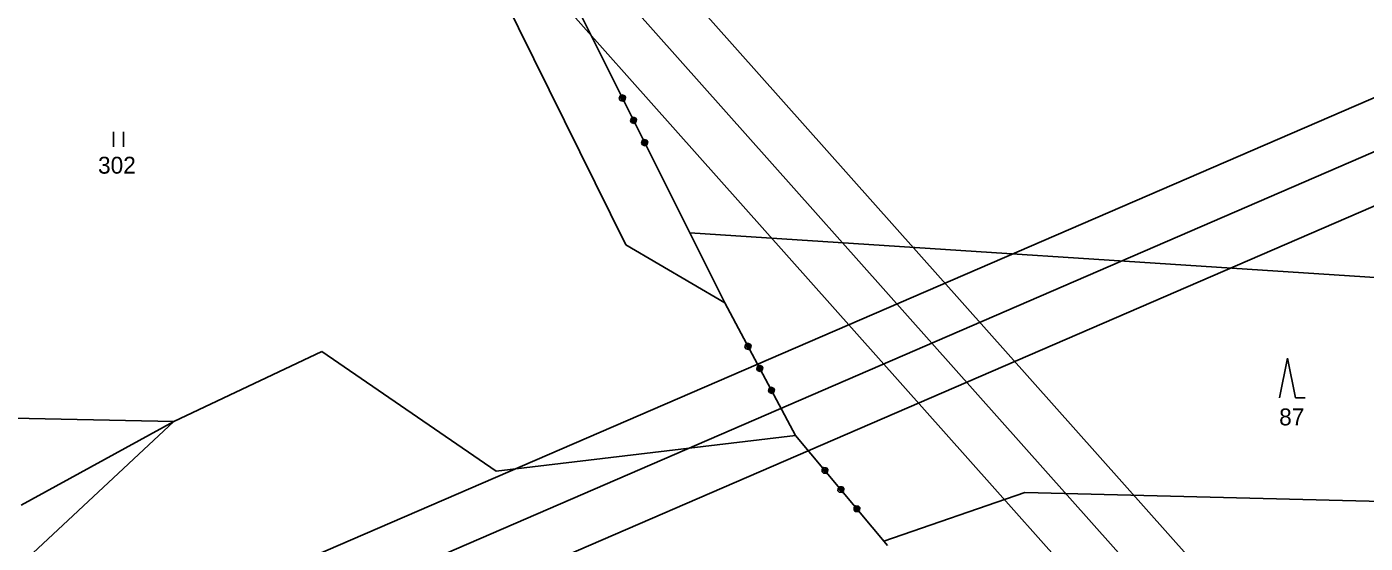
# Model space of a CAD drawing. Extents: x -866656 to -858817, y -1041816 to -1038653.
# Drawn here: x -865224.7 to -865090.2, y -1040508.5 to -1040456.6 of the extents above; entities that cross this region are included whole.
import ezdxf

# ---------------------------------------------------------------- set-up
doc = ezdxf.new("R2010")
doc.units = 0
for name, color, linetype in [('tisk ramy', 7, 'Continuous'), ('Vrstva 1', 7, 'Continuous'), ('Vrstva 3', 7, 'Continuous')]:
    doc.layers.add(name, color=color, linetype=linetype)

msp = doc.modelspace()

# ---------------------------------------------------------------- linework, layer by layer
at = {"layer": 'tisk ramy'}
for points in [[(-865732.63, -1039823.16), (-864894.8, -1040764.23), (-864672.98, -1040566.75), (-865510.81, -1039625.68)], [(-865511.22, -1039632.74), (-864680.04, -1040566.34), (-864894.39, -1040757.18), (-865725.57, -1039823.57)], [(-865718.52, -1039823.98), (-865030.3, -1040597.01), (-864823.41, -1040412.82), (-865511.63, -1039639.79)], [(-865511.63, -1039639.79), (-864823.41, -1040412.82), (-865030.3, -1040597.01), (-865718.52, -1039823.98)], [(-865224.28, -1040522.07), (-864724.07, -1041678.52), (-864451.49, -1041560.62), (-864951.69, -1040404.17)], [(-864954.3, -1040410.74), (-864458.06, -1041558.01), (-864721.47, -1041671.94), (-865217.7, -1040524.67)], [(-865211.14, -1040527.28), (-864800.25, -1041477.22), (-864546.01, -1041367.26), (-864956.9, -1040417.31)], [(-864956.9, -1040417.31), (-864546.01, -1041367.26), (-864800.25, -1041477.22), (-865211.14, -1040527.28)]]:
    msp.add_lwpolyline(points, close=True, dxfattribs=at)
at = {"layer": 'Vrstva 1'}
for p, q in [((-865164.46, -1040478.49), (-865186.01, -1040434.88)), ((-865215.96, -1040468.62), (-865215.96, -1040467.12)), ((-865214.96, -1040467.12), (-865214.96, -1040468.62)), ((-865058.05, -1040483.78), (-865158.05, -1040477.27)), ((-865154.52, -1040484.32), (-865164.46, -1040478.49)), ((-865209.89, -1040496.23), (-865195.03, -1040489.18)), ((-865195.03, -1040489.18), (-865177.49, -1040501.21)), ((-865098.78, -1040493.85), (-865097.98, -1040489.85)), ((-865097.98, -1040489.85), (-865097.18, -1040493.85)), ((-865097.18, -1040493.85), (-865096.18, -1040493.85)), ((-865234.53, -1040495.7), (-865209.89, -1040496.23)), ((-865225.24, -1040504.64), (-865209.89, -1040496.23)), ((-865209.89, -1040496.23), (-865224.07, -1040509.48)), ((-865177.49, -1040501.21), (-865147.41, -1040497.64)), ((-865124.38, -1040503.38), (-865138.53, -1040508.25)), ((-865078.37, -1040504.54), (-865124.38, -1040503.38))]:
    msp.add_line(p, q, dxfattribs=at)
at = {"layer": 'Vrstva 3'}
for p, q in [((-865172.79, -1040447.78), (-865154.52, -1040484.32)), ((-865172.79, -1040447.78), (-865154.52, -1040484.32)), ((-865165.13, -1040463.77), (-865165.04, -1040463.5)), ((-865165.13, -1040463.77), (-865165.04, -1040463.5)), ((-865165.04, -1040463.95), (-865165.13, -1040463.77)), ((-865165.04, -1040463.95), (-865165.13, -1040463.77)), ((-865165.04, -1040463.5), (-865164.86, -1040463.41)), ((-865165.04, -1040463.5), (-865164.86, -1040463.41)), ((-865165.04, -1040463.72), (-865164.68, -1040463.55)), ((-865165.04, -1040463.72), (-865164.68, -1040463.55)), ((-865165, -1040463.59), (-865165.04, -1040463.72)), ((-865165, -1040463.59), (-865165.04, -1040463.72)), ((-865164.77, -1040464.04), (-865165.04, -1040463.95)), ((-865164.77, -1040464.04), (-865165.04, -1040463.95)), ((-865164.82, -1040463.5), (-865165, -1040463.59)), ((-865164.82, -1040463.5), (-865165, -1040463.59)), ((-865164.64, -1040463.64), (-865165, -1040463.81)), ((-865164.64, -1040463.64), (-865165, -1040463.81)), ((-865164.59, -1040463.72), (-865164.95, -1040463.9)), ((-865164.59, -1040463.72), (-865164.95, -1040463.9)), ((-865164.95, -1040463.9), (-865164.82, -1040463.95)), ((-865164.95, -1040463.9), (-865164.82, -1040463.95)), ((-865164.86, -1040463.41), (-865164.59, -1040463.5)), ((-865164.86, -1040463.41), (-865164.59, -1040463.5)), ((-865164.82, -1040463.95), (-865164.64, -1040463.86)), ((-865164.82, -1040463.95), (-865164.64, -1040463.86)), ((-865164.59, -1040463.95), (-865164.77, -1040464.04)), ((-865164.59, -1040463.95), (-865164.77, -1040464.04)), ((-865164.68, -1040463.55), (-865164.59, -1040463.72)), ((-865164.68, -1040463.55), (-865164.59, -1040463.72)), ((-865164.59, -1040463.5), (-865164.5, -1040463.68)), ((-865164.59, -1040463.5), (-865164.5, -1040463.68)), ((-865164.5, -1040463.68), (-865164.59, -1040463.95)), ((-865164.5, -1040463.68), (-865164.59, -1040463.95)), ((-865164.01, -1040466.01), (-865163.92, -1040465.74)), ((-865164.01, -1040466.01), (-865163.92, -1040465.74)), ((-865163.92, -1040466.18), (-865164.01, -1040466.01)), ((-865163.92, -1040466.18), (-865164.01, -1040466.01)), ((-865163.92, -1040465.74), (-865163.74, -1040465.65)), ((-865163.92, -1040465.74), (-865163.74, -1040465.65)), ((-865163.92, -1040465.96), (-865163.57, -1040465.78)), ((-865163.92, -1040465.96), (-865163.57, -1040465.78)), ((-865163.88, -1040465.83), (-865163.92, -1040465.96)), ((-865163.88, -1040465.83), (-865163.92, -1040465.96)), ((-865163.66, -1040466.27), (-865163.92, -1040466.18)), ((-865163.66, -1040466.27), (-865163.92, -1040466.18)), ((-865163.7, -1040465.74), (-865163.88, -1040465.83)), ((-865163.7, -1040465.74), (-865163.88, -1040465.83)), ((-865163.52, -1040465.87), (-865163.88, -1040466.05)), ((-865163.52, -1040465.87), (-865163.88, -1040466.05)), ((-865163.48, -1040465.96), (-865163.83, -1040466.14)), ((-865163.48, -1040465.96), (-865163.83, -1040466.14)), ((-865163.83, -1040466.14), (-865163.7, -1040466.18)), ((-865163.83, -1040466.14), (-865163.7, -1040466.18)), ((-865163.74, -1040465.65), (-865163.48, -1040465.74)), ((-865163.74, -1040465.65), (-865163.48, -1040465.74)), ((-865163.7, -1040466.18), (-865163.52, -1040466.09)), ((-865163.7, -1040466.18), (-865163.52, -1040466.09)), ((-865163.48, -1040466.18), (-865163.66, -1040466.27)), ((-865163.48, -1040466.18), (-865163.66, -1040466.27)), ((-865163.57, -1040465.78), (-865163.48, -1040465.96)), ((-865163.57, -1040465.78), (-865163.48, -1040465.96)), ((-865163.48, -1040465.74), (-865163.39, -1040465.92)), ((-865163.48, -1040465.74), (-865163.39, -1040465.92)), ((-865163.39, -1040465.92), (-865163.48, -1040466.18)), ((-865163.39, -1040465.92), (-865163.48, -1040466.18)), ((-865162.89, -1040468.24), (-865162.81, -1040467.97)), ((-865162.89, -1040468.24), (-865162.81, -1040467.97)), ((-865162.81, -1040467.97), (-865162.63, -1040467.88)), ((-865162.81, -1040467.97), (-865162.63, -1040467.88)), ((-865162.81, -1040468.2), (-865162.45, -1040468.02)), ((-865162.81, -1040468.2), (-865162.45, -1040468.02)), ((-865162.58, -1040467.97), (-865162.76, -1040468.06)), ((-865162.58, -1040467.97), (-865162.76, -1040468.06)), ((-865162.63, -1040467.88), (-865162.36, -1040467.97)), ((-865162.63, -1040467.88), (-865162.36, -1040467.97)), ((-865162.45, -1040468.02), (-865162.36, -1040468.2)), ((-865162.45, -1040468.02), (-865162.36, -1040468.2)), ((-865162.36, -1040467.97), (-865162.27, -1040468.15)), ((-865162.36, -1040467.97), (-865162.27, -1040468.15)), ((-865162.81, -1040468.42), (-865162.89, -1040468.24)), ((-865162.81, -1040468.42), (-865162.89, -1040468.24)), ((-865162.76, -1040468.06), (-865162.81, -1040468.2)), ((-865162.76, -1040468.06), (-865162.81, -1040468.2)), ((-865162.54, -1040468.51), (-865162.81, -1040468.42)), ((-865162.54, -1040468.51), (-865162.81, -1040468.42)), ((-865162.4, -1040468.11), (-865162.76, -1040468.29)), ((-865162.4, -1040468.11), (-865162.76, -1040468.29)), ((-865162.36, -1040468.2), (-865162.71, -1040468.38)), ((-865162.36, -1040468.2), (-865162.71, -1040468.38)), ((-865162.71, -1040468.38), (-865162.58, -1040468.42)), ((-865162.71, -1040468.38), (-865162.58, -1040468.42)), ((-865162.58, -1040468.42), (-865162.4, -1040468.33)), ((-865162.58, -1040468.42), (-865162.4, -1040468.33)), ((-865162.36, -1040468.42), (-865162.54, -1040468.51)), ((-865162.36, -1040468.42), (-865162.54, -1040468.51)), ((-865162.27, -1040468.15), (-865162.36, -1040468.42)), ((-865162.27, -1040468.15), (-865162.36, -1040468.42)), ((-865154.52, -1040484.32), (-865147.41, -1040497.64)), ((-865154.52, -1040484.32), (-865147.41, -1040497.64)), ((-865152.5, -1040488.74), (-865152.42, -1040488.47)), ((-865152.5, -1040488.74), (-865152.42, -1040488.47)), ((-865152.41, -1040488.92), (-865152.5, -1040488.74)), ((-865152.41, -1040488.92), (-865152.5, -1040488.74)), ((-865152.42, -1040488.47), (-865152.24, -1040488.37)), ((-865152.42, -1040488.47), (-865152.24, -1040488.37)), ((-865152.41, -1040488.69), (-865152.06, -1040488.5)), ((-865152.41, -1040488.69), (-865152.06, -1040488.5)), ((-865152.37, -1040488.56), (-865152.41, -1040488.69)), ((-865152.37, -1040488.56), (-865152.41, -1040488.69)), ((-865152.14, -1040489), (-865152.41, -1040488.92)), ((-865152.14, -1040489), (-865152.41, -1040488.92)), ((-865152.2, -1040488.46), (-865152.37, -1040488.56)), ((-865152.2, -1040488.46), (-865152.37, -1040488.56)), ((-865152.01, -1040488.59), (-865152.36, -1040488.78)), ((-865152.01, -1040488.59), (-865152.36, -1040488.78)), ((-865151.96, -1040488.68), (-865152.32, -1040488.87)), ((-865151.96, -1040488.68), (-865152.32, -1040488.87)), ((-865152.32, -1040488.87), (-865152.18, -1040488.91)), ((-865152.32, -1040488.87), (-865152.18, -1040488.91)), ((-865152.24, -1040488.37), (-865151.97, -1040488.46)), ((-865152.24, -1040488.37), (-865151.97, -1040488.46)), ((-865152.18, -1040488.91), (-865152.01, -1040488.82)), ((-865152.18, -1040488.91), (-865152.01, -1040488.82)), ((-865151.96, -1040488.9), (-865152.14, -1040489)), ((-865151.96, -1040488.9), (-865152.14, -1040489)), ((-865152.06, -1040488.5), (-865151.96, -1040488.68)), ((-865152.06, -1040488.5), (-865151.96, -1040488.68)), ((-865151.97, -1040488.46), (-865151.88, -1040488.63)), ((-865151.97, -1040488.46), (-865151.88, -1040488.63)), ((-865151.88, -1040488.63), (-865151.96, -1040488.9)), ((-865151.88, -1040488.63), (-865151.96, -1040488.9)), ((-865151.32, -1040490.94), (-865151.24, -1040490.67)), ((-865151.32, -1040490.94), (-865151.24, -1040490.67)), ((-865151.24, -1040490.67), (-865151.07, -1040490.58)), ((-865151.24, -1040490.67), (-865151.07, -1040490.58)), ((-865151.23, -1040490.9), (-865150.88, -1040490.71)), ((-865151.23, -1040490.9), (-865150.88, -1040490.71)), ((-865151.19, -1040490.76), (-865151.23, -1040490.9)), ((-865151.19, -1040490.76), (-865151.23, -1040490.9)), ((-865151.02, -1040490.67), (-865151.19, -1040490.76)), ((-865151.02, -1040490.67), (-865151.19, -1040490.76)), ((-865150.83, -1040490.8), (-865151.19, -1040490.98)), ((-865150.83, -1040490.8), (-865151.19, -1040490.98)), ((-865150.79, -1040490.89), (-865151.14, -1040491.07)), ((-865150.79, -1040490.89), (-865151.14, -1040491.07)), ((-865151.07, -1040490.58), (-865150.79, -1040490.66)), ((-865151.07, -1040490.58), (-865150.79, -1040490.66)), ((-865150.88, -1040490.71), (-865150.79, -1040490.89)), ((-865150.88, -1040490.71), (-865150.79, -1040490.89)), ((-865150.79, -1040490.66), (-865150.7, -1040490.84)), ((-865150.79, -1040490.66), (-865150.7, -1040490.84)), ((-865150.7, -1040490.84), (-865150.78, -1040491.11)), ((-865150.7, -1040490.84), (-865150.78, -1040491.11)), ((-865151.23, -1040491.12), (-865151.32, -1040490.94)), ((-865151.23, -1040491.12), (-865151.32, -1040490.94)), ((-865150.96, -1040491.2), (-865151.23, -1040491.12)), ((-865150.96, -1040491.2), (-865151.23, -1040491.12)), ((-865151.14, -1040491.07), (-865151.01, -1040491.11)), ((-865151.14, -1040491.07), (-865151.01, -1040491.11)), ((-865151.01, -1040491.11), (-865150.83, -1040491.02)), ((-865151.01, -1040491.11), (-865150.83, -1040491.02)), ((-865150.78, -1040491.11), (-865150.96, -1040491.2)), ((-865150.78, -1040491.11), (-865150.96, -1040491.2)), ((-865150.15, -1040493.15), (-865150.06, -1040492.88)), ((-865150.15, -1040493.15), (-865150.06, -1040492.88)), ((-865150.05, -1040493.33), (-865150.15, -1040493.15)), ((-865150.05, -1040493.33), (-865150.15, -1040493.15)), ((-865150.06, -1040492.88), (-865149.89, -1040492.79)), ((-865150.06, -1040492.88), (-865149.89, -1040492.79)), ((-865150.06, -1040493.1), (-865149.71, -1040492.91)), ((-865150.06, -1040493.1), (-865149.71, -1040492.91)), ((-865150.02, -1040492.97), (-865150.06, -1040493.1)), ((-865150.02, -1040492.97), (-865150.06, -1040493.1)), ((-865149.78, -1040493.41), (-865150.05, -1040493.33)), ((-865149.78, -1040493.41), (-865150.05, -1040493.33)), ((-865149.84, -1040492.87), (-865150.02, -1040492.97)), ((-865149.84, -1040492.87), (-865150.02, -1040492.97)), ((-865149.66, -1040493), (-865150.01, -1040493.19)), ((-865149.66, -1040493), (-865150.01, -1040493.19)), ((-865149.61, -1040493.09), (-865149.96, -1040493.28)), ((-865149.61, -1040493.09), (-865149.96, -1040493.28)), ((-865149.96, -1040493.28), (-865149.83, -1040493.32)), ((-865149.96, -1040493.28), (-865149.83, -1040493.32)), ((-865149.89, -1040492.79), (-865149.62, -1040492.87)), ((-865149.89, -1040492.79), (-865149.62, -1040492.87)), ((-865149.83, -1040493.32), (-865149.65, -1040493.23)), ((-865149.83, -1040493.32), (-865149.65, -1040493.23)), ((-865149.6, -1040493.31), (-865149.78, -1040493.41)), ((-865149.6, -1040493.31), (-865149.78, -1040493.41)), ((-865149.71, -1040492.91), (-865149.61, -1040493.09)), ((-865149.71, -1040492.91), (-865149.61, -1040493.09)), ((-865149.62, -1040492.87), (-865149.52, -1040493.04)), ((-865149.62, -1040492.87), (-865149.52, -1040493.04)), ((-865149.52, -1040493.04), (-865149.6, -1040493.31)), ((-865149.52, -1040493.04), (-865149.6, -1040493.31)), ((-865147.41, -1040497.64), (-865138.17, -1040508.68)), ((-865147.41, -1040497.64), (-865138.17, -1040508.68)), ((-865144.75, -1040501.28), (-865144.73, -1040501)), ((-865144.75, -1040501.28), (-865144.73, -1040501)), ((-865144.62, -1040501.44), (-865144.75, -1040501.28)), ((-865144.62, -1040501.44), (-865144.75, -1040501.28)), ((-865144.73, -1040501), (-865144.57, -1040500.87)), ((-865144.73, -1040501), (-865144.57, -1040500.87)), ((-865144.68, -1040501.22), (-865144.37, -1040500.96)), ((-865144.68, -1040501.22), (-865144.37, -1040500.96)), ((-865144.66, -1040501.08), (-865144.68, -1040501.22)), ((-865144.66, -1040501.08), (-865144.68, -1040501.22)), ((-865144.51, -1040500.95), (-865144.66, -1040501.08)), ((-865144.51, -1040500.95), (-865144.66, -1040501.08)), ((-865144.34, -1040501.46), (-865144.62, -1040501.44)), ((-865144.34, -1040501.46), (-865144.62, -1040501.44)), ((-865144.31, -1040501.04), (-865144.61, -1040501.29)), ((-865144.31, -1040501.04), (-865144.61, -1040501.29)), ((-865144.57, -1040500.87), (-865144.29, -1040500.9)), ((-865144.57, -1040500.87), (-865144.29, -1040500.9)), ((-865144.24, -1040501.11), (-865144.55, -1040501.37)), ((-865144.24, -1040501.11), (-865144.55, -1040501.37)), ((-865144.55, -1040501.37), (-865144.41, -1040501.38)), ((-865144.55, -1040501.37), (-865144.41, -1040501.38)), ((-865144.41, -1040501.38), (-865144.25, -1040501.26)), ((-865144.41, -1040501.38), (-865144.25, -1040501.26)), ((-865144.37, -1040500.96), (-865144.24, -1040501.11)), ((-865144.37, -1040500.96), (-865144.24, -1040501.11)), ((-865144.19, -1040501.33), (-865144.34, -1040501.46)), ((-865144.19, -1040501.33), (-865144.34, -1040501.46)), ((-865144.29, -1040500.9), (-865144.16, -1040501.05)), ((-865144.29, -1040500.9), (-865144.16, -1040501.05)), ((-865144.16, -1040501.05), (-865144.19, -1040501.33)), ((-865144.16, -1040501.05), (-865144.19, -1040501.33)), ((-865143.15, -1040503.2), (-865143.12, -1040502.92)), ((-865143.15, -1040503.2), (-865143.12, -1040502.92)), ((-865143.12, -1040502.92), (-865142.97, -1040502.79)), ((-865143.12, -1040502.92), (-865142.97, -1040502.79)), ((-865143.07, -1040503.14), (-865142.77, -1040502.88)), ((-865143.07, -1040503.14), (-865142.77, -1040502.88)), ((-865143.06, -1040502.99), (-865143.07, -1040503.14)), ((-865143.06, -1040502.99), (-865143.07, -1040503.14)), ((-865142.91, -1040502.86), (-865143.06, -1040502.99)), ((-865142.91, -1040502.86), (-865143.06, -1040502.99)), ((-865142.7, -1040502.95), (-865143.01, -1040503.21)), ((-865142.7, -1040502.95), (-865143.01, -1040503.21)), ((-865142.97, -1040502.79), (-865142.69, -1040502.81)), ((-865142.97, -1040502.79), (-865142.69, -1040502.81)), ((-865142.77, -1040502.88), (-865142.64, -1040503.03)), ((-865142.77, -1040502.88), (-865142.64, -1040503.03)), ((-865142.69, -1040502.81), (-865142.56, -1040502.97)), ((-865142.69, -1040502.81), (-865142.56, -1040502.97)), ((-865142.56, -1040502.97), (-865142.58, -1040503.25)), ((-865142.56, -1040502.97), (-865142.58, -1040503.25)), ((-865143.02, -1040503.35), (-865143.15, -1040503.2)), ((-865143.02, -1040503.35), (-865143.15, -1040503.2)), ((-865142.74, -1040503.38), (-865143.02, -1040503.35)), ((-865142.74, -1040503.38), (-865143.02, -1040503.35)), ((-865142.64, -1040503.03), (-865142.94, -1040503.29)), ((-865142.64, -1040503.03), (-865142.94, -1040503.29)), ((-865142.94, -1040503.29), (-865142.8, -1040503.3)), ((-865142.94, -1040503.29), (-865142.8, -1040503.3)), ((-865142.8, -1040503.3), (-865142.65, -1040503.17)), ((-865142.8, -1040503.3), (-865142.65, -1040503.17)), ((-865142.58, -1040503.25), (-865142.74, -1040503.38)), ((-865142.58, -1040503.25), (-865142.74, -1040503.38)), ((-865141.54, -1040505.12), (-865141.52, -1040504.83)), ((-865141.54, -1040505.12), (-865141.52, -1040504.83)), ((-865141.42, -1040505.27), (-865141.54, -1040505.12)), ((-865141.42, -1040505.27), (-865141.54, -1040505.12)), ((-865141.52, -1040504.83), (-865141.36, -1040504.71)), ((-865141.52, -1040504.83), (-865141.36, -1040504.71)), ((-865141.47, -1040505.05), (-865141.16, -1040504.8)), ((-865141.47, -1040505.05), (-865141.16, -1040504.8)), ((-865141.45, -1040504.91), (-865141.47, -1040505.05)), ((-865141.45, -1040504.91), (-865141.47, -1040505.05)), ((-865141.3, -1040504.78), (-865141.45, -1040504.91)), ((-865141.3, -1040504.78), (-865141.45, -1040504.91)), ((-865141.13, -1040505.29), (-865141.42, -1040505.27)), ((-865141.13, -1040505.29), (-865141.42, -1040505.27)), ((-865141.1, -1040504.87), (-865141.4, -1040505.13)), ((-865141.1, -1040504.87), (-865141.4, -1040505.13)), ((-865141.36, -1040504.71), (-865141.08, -1040504.73)), ((-865141.36, -1040504.71), (-865141.08, -1040504.73)), ((-865141.03, -1040504.95), (-865141.34, -1040505.21)), ((-865141.03, -1040504.95), (-865141.34, -1040505.21)), ((-865141.34, -1040505.21), (-865141.2, -1040505.22)), ((-865141.34, -1040505.21), (-865141.2, -1040505.22)), ((-865141.2, -1040505.22), (-865141.04, -1040505.09)), ((-865141.2, -1040505.22), (-865141.04, -1040505.09)), ((-865141.16, -1040504.8), (-865141.03, -1040504.95)), ((-865141.16, -1040504.8), (-865141.03, -1040504.95)), ((-865140.98, -1040505.17), (-865141.13, -1040505.29)), ((-865140.98, -1040505.17), (-865141.13, -1040505.29)), ((-865141.08, -1040504.73), (-865140.96, -1040504.88)), ((-865141.08, -1040504.73), (-865140.96, -1040504.88)), ((-865140.96, -1040504.88), (-865140.98, -1040505.17)), ((-865140.96, -1040504.88), (-865140.98, -1040505.17))]:
    msp.add_line(p, q, dxfattribs=at)

# ---------------------------------------------------------------- texts
at = {"layer": 'Vrstva 1'}
for s, p in [('302', (-865217.52, -1040471.32)), ('87', (-865098.81, -1040496.62))]:
    msp.add_text(s, height=1.7, dxfattribs=at).set_placement(p)

doc.saveas('drawing.dxf')
